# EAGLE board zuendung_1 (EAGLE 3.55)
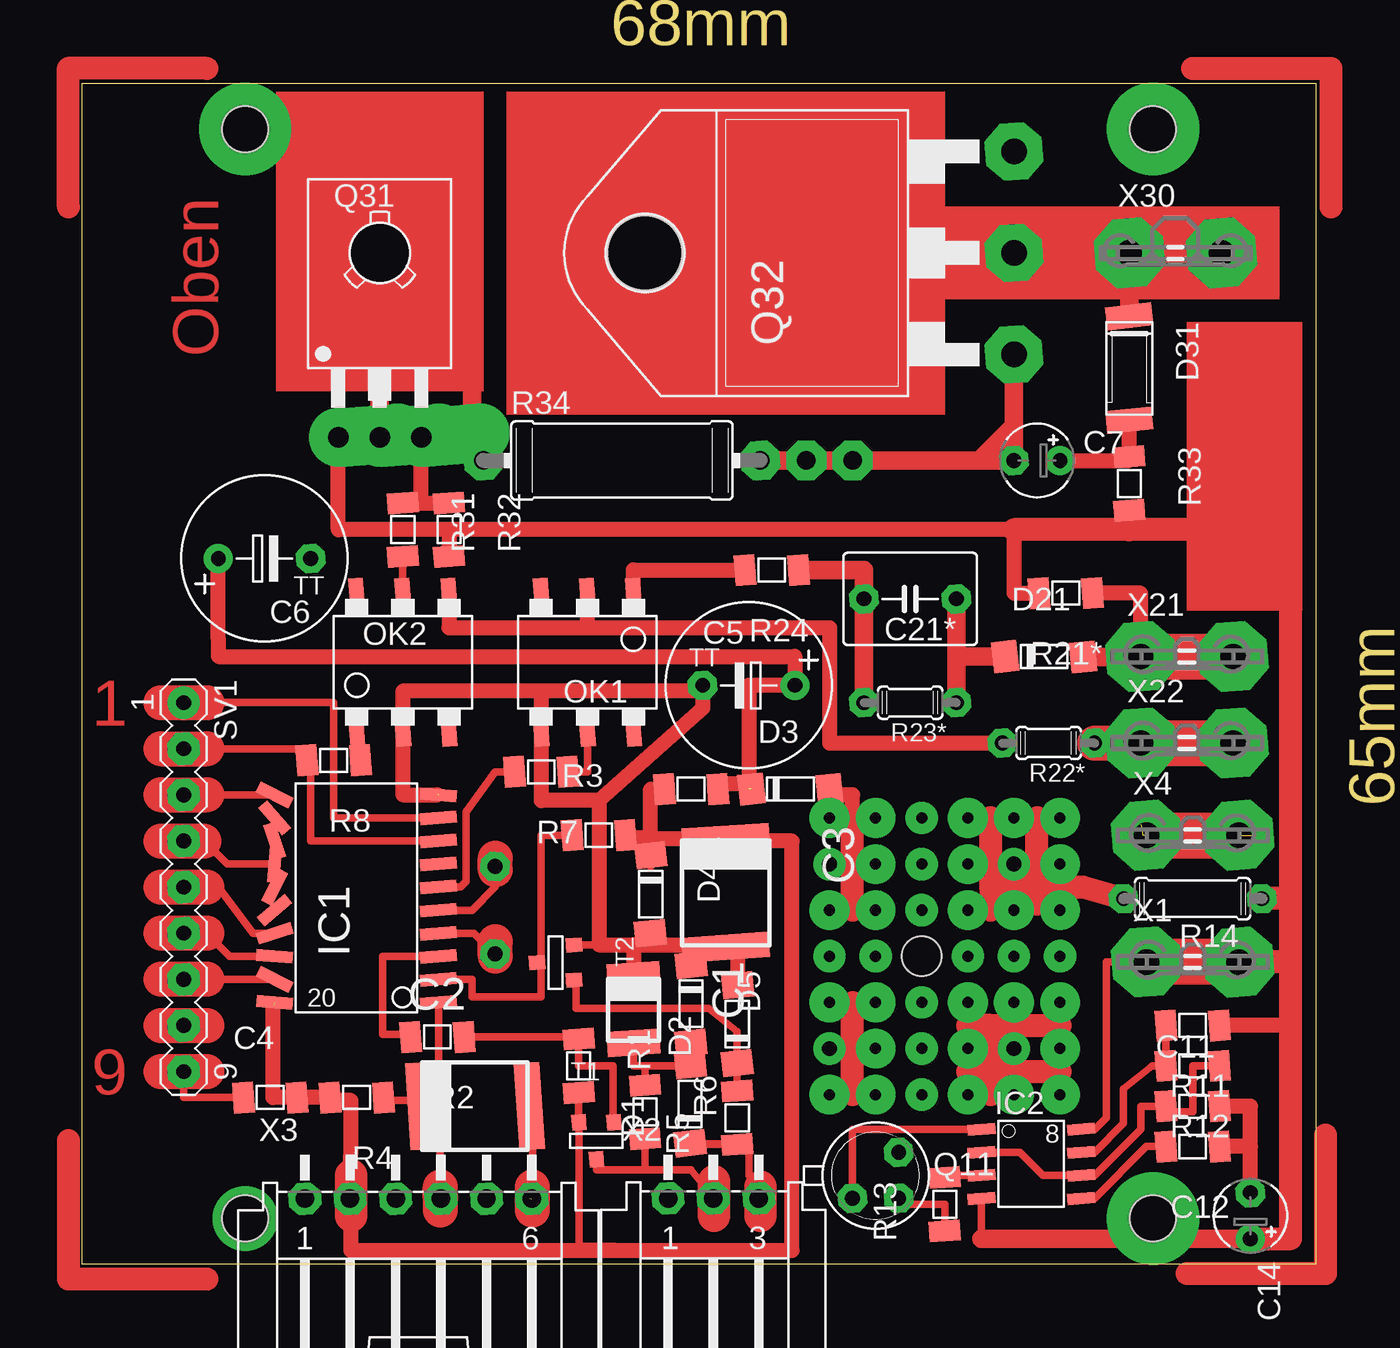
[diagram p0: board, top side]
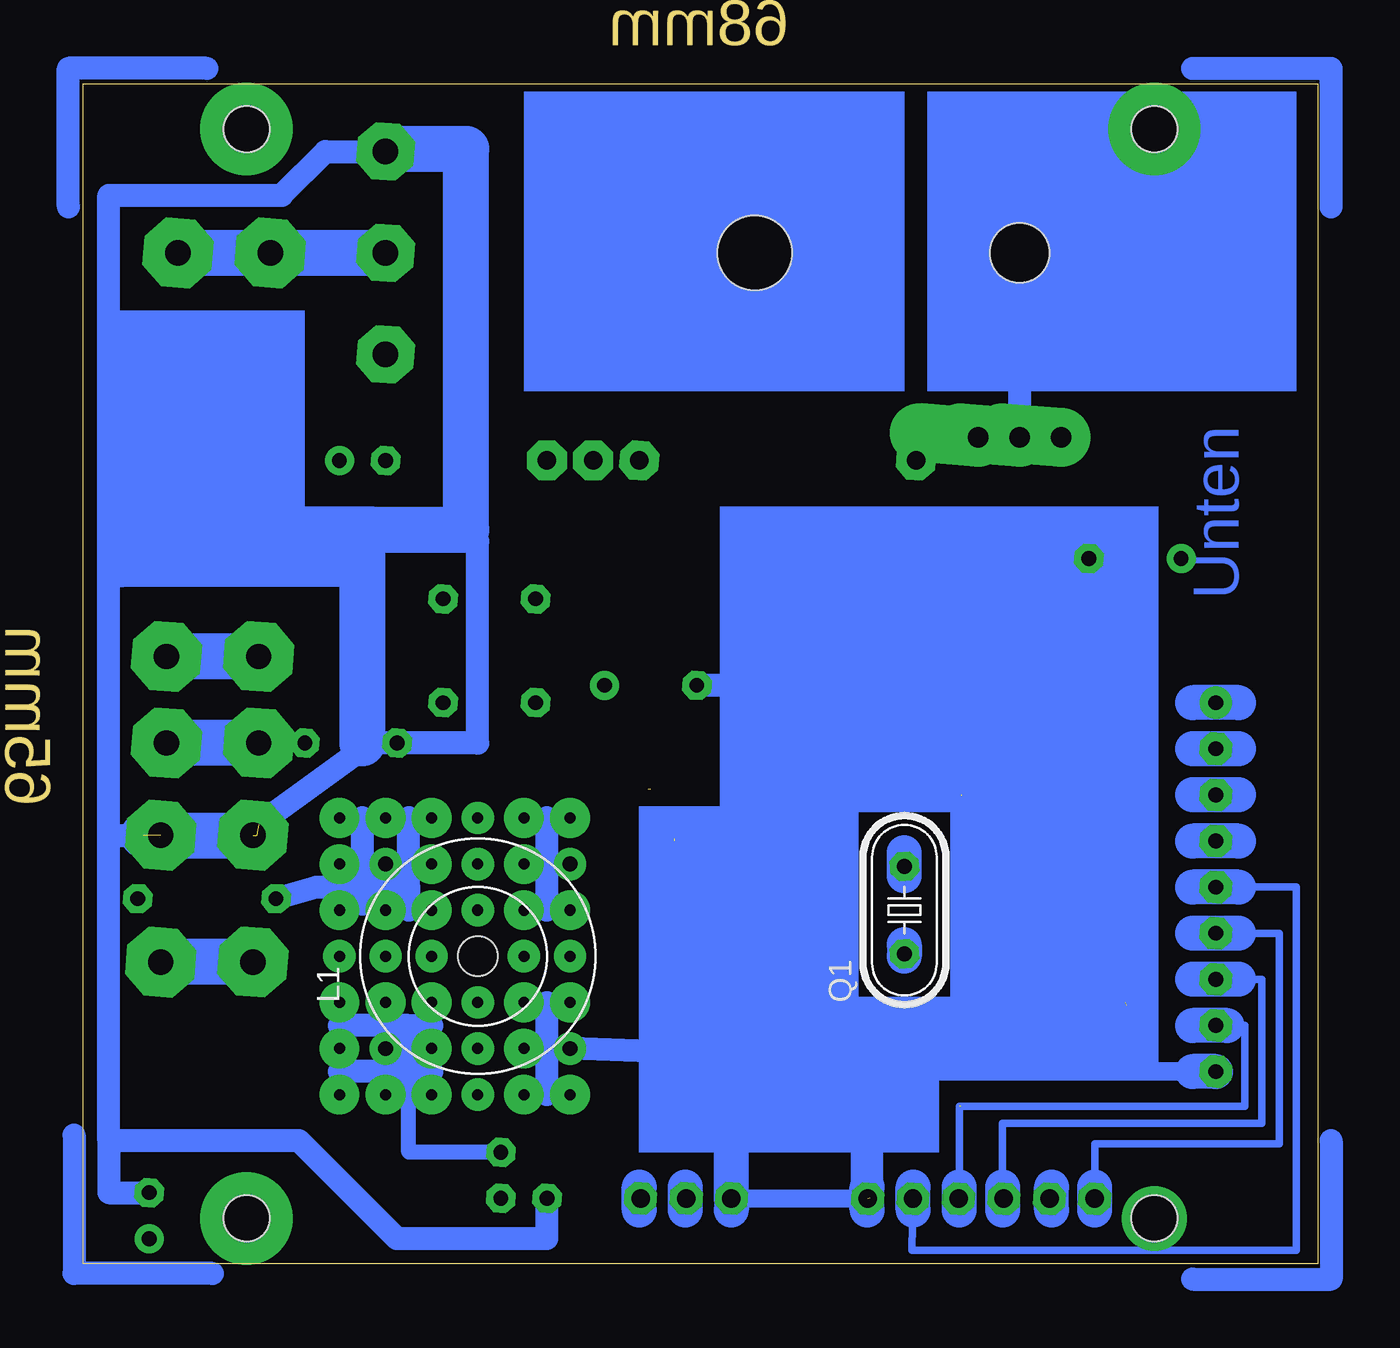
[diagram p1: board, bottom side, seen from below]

Size 68 x 65 mm. Coordinates in mm from the lower left corner, seen from the top.
Outline: 0,0 68,0 68,65 0,65 0,0
Copper layers used: Top, Bottom
Holes 2.54 mm at 9,2.5 59,2.5 59,62.5 9,62.5

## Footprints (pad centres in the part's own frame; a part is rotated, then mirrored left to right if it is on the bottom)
 = smd 1.4 x 2.9 rotated 3.8:  -1.8,0 | smd 1.4 x 2.9 rotated 4:  1.9,0
KO6X5 = smd 1.4 x 4.8 rotated 3.8:  -3,0 | smd 1.4 x 4.8 rotated 4:  3,0
06 = smd 1.143 x 1.702 rotated 4.4:  1.473,0 | smd 1.143 x 1.702 rotated 4.3:  -1.473,0
5D9 = drill 0.813 pad 1.6 octagon:  -2.54,0 | drill 0.813 pad 1.6 round:  2.54,0
2D4 = drill 0.813 pad 1.6 octagon:  -1.27,0 | drill 0.813 pad 1.6 round:  1.27,0
B5 = drill 0.813 pad 1.6 octagon:  -2.54,0;  2.54,0
D-80 = smd 1.397 x 1.702 rotated 6.6:  -2.388,0 | smd 1.397 x 1.702 rotated 5.7:  1.905,-0.025
LF = smd 1.27 x 2.54 rotated 6.6:  -2.857,0 | smd 1.27 x 2.54 rotated 5.7:  2.857,0
-20 = smd 0.66 x 2.007 rotated 4.3:  -5.08,-4.496;  6.35,-4.496 | smd 0.66 x 2.007 rotated 4.4:  -3.81,-4.496;  -5.08,4.521 | smd 0.66 x 2.007 rotated 4.5:  -2.54,-4.496 | smd 0.66 x 2.007 rotated 4.6:  -1.27,-4.496 | smd 0.66 x 2.007 rotated 4.7:  0,-4.496;  1.27,-4.496 | smd 0.66 x 2.007 rotated 4.8:  2.54,-4.496 | smd 0.66 x 2.007 rotated 4.9:  3.81,-4.496 | smd 0.66 x 2.007 rotated 5:  5.08,-4.496 | smd 0.66 x 2.007 rotated 49.3:  5.08,4.521 | smd 0.66 x 2.007 rotated 26.8:  6.35,4.521 | smd 0.66 x 2.007 rotated 71.8:  3.81,4.521 | smd 0.66 x 2.007 rotated 94.3:  2.54,4.521 | smd 0.66 x 2.007 rotated 116.8:  1.27,4.521 | smd 0.66 x 2.007 rotated 139.3:  0,4.521 | smd 0.66 x 2.007 rotated 161.8:  -1.27,4.521 | smd 0.66 x 2.007 rotated 184.3:  -2.54,4.521 | smd 0.66 x 2.007 rotated 206.8:  -3.81,4.521
-8 = smd 0.61 x 1.524 rotated 4.3:  -1.27,-2.743 | smd 0.61 x 1.524 rotated 4.9:  -1.27,2.743 | smd 0.61 x 1.524 rotated 4.4:  0,-2.743 | smd 0.61 x 1.524 rotated 4.5:  1.27,-2.743 | smd 0.61 x 1.524 rotated 4.8:  0,2.743 | smd 0.61 x 1.524 rotated 4.7:  1.27,2.743;  2.54,2.743 | smd 0.61 x 1.524 rotated 4.6:  2.54,-2.743
10X10 = drill 0.813 pad 1.778 round:  -5.08,5.08;  5.08,5.08;  5.08,-5.08;  -5.08,-5.08 | hole 2.184: 0,0
IC06 = smd 0.813 x 1.676 rotated 4.7:  0,3.81;  -2.54,3.81 | smd 0.813 x 1.676 rotated 4.6:  2.54,3.81 | smd 0.813 x 1.676 rotated 4.4:  0,-3.81 | smd 0.813 x 1.676 rotated 4.3:  -2.54,-3.81 | smd 0.813 x 1.676 rotated 4.5:  2.54,-3.81
49U-V = drill 0.813 pad 1.6 octagon:  -2.413,0;  2.413,0
18 = drill 0.813 pad 1.6 octagon:  -1.27,-1.27;  1.27,-1.27;  1.27,1.27
126 = drill 1.118 pad 3.251 offset:  -2.286,-5.08;  0,-5.08;  2.286,-5.08 | hole 3.302: 0,5.08
P3 = drill 1.397 pad 3.15 octagon:  -5.588,-7.62;  0,-7.62;  5.588,-7.62 | hole 4.115: 0,12.7
07/7 = drill 0.813 pad 1.6 octagon:  -3.81,0;  3.81,0
04/5 = drill 0.813 pad 1.6 octagon:  -2.54,0;  2.54,0
14/15 = drill 1.016 pad 2.159 octagon:  -7.62,0;  7.62,0
09-1 = drill 0.813 pad 1.778 round:  -10.16,0 | drill 0.813 pad 1.778 octagon:  -7.62,0;  -5.08,0;  -2.54,0;  0,0;  2.54,0;  5.08,0;  7.62,0;  10.16,0
T-23 = smd 0.787 x 0.889 rotated 4.4:  0.991,1.016 | smd 0.787 x 0.889 rotated 4.3:  -0.94,1.016 | smd 0.787 x 0.889 rotated 4.5:  0.025,-1.016
4,8 = drill 1.397 pad 3.81 octagon:  -2.54,0;  2.54,0
FW3 = drill 1.016 pad 1.778 octagon:  0,1.905;  2.489,1.905;  5.004,1.905
FW6 = drill 1.016 pad 1.778 octagon:  0,1.905;  2.489,1.905;  5.004,1.905;  7.493,1.905;  10.008,1.905;  12.497,1.905
6,3 = drill 1.397 pad 3.81 octagon:  -2.54,0;  2.54,0

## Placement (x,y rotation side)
C1  2æ2/16  []  30.38,14.08 270 top
C2  22/16  [KO6X5]  21.65,8.68 0 top
C3  22/10  [KO6X5]  35.47,20.43 270 top
C4  100n  [06]  10.38,9.16 0 top
C5  470/10  [5D9]  36.73,31.86 0 top
C6  470/10  [5D9]  10.06,38.85 180 top
C7  0,22  [2D4]  52.61,44.24 0 top
C11  2n7  [06]  61.18,8.68 0 top
C12  10n  [06]  61.18,6.46 180 top
C14  47/25  [2D4]  64.36,2.65 270 top
C21*  47n*  [B5]  45.62,36.62 180 top
D1  LL4148  [D-80]  33.5,9.03 90 top
D2  LL4148  [D-80]  36.1,13.45 90 top
D3  LL4148  [D-80]  39.27,26.15 0 top
D4  5V1  [D-80]  31.34,20.11 270 top
D5  LL4148  [D-80]  33.56,14.08 270 top
D21  LL4148  [D-80]  53.24,33.45 0 top
D31  BYM10  [LF]  57.69,49.33 270 top
IC1  AT90S2313  [-20]  15.14,19.48 90 top
IC2  555  [-8]  52.29,6.14 270 top
L1  T1:1/10  [10X10]  46.26,16.94 90 bottom
OK1  SFH601-2SO  [IC06]  27.84,33.13 180 top
OK2  SFH601-2SO  [IC06]  17.68,33.13 0 top
Q1  10.000  [49U-V]  22.77,19.48 90 bottom
Q11  BCY59  [18]  43.72,4.88 0 top
Q31  BD236  [126]  16.41,50.59 0 top
Q32  BD249  [P3]  43.72,55.67 90 top
R1  4K7  [06]  27.37,10.91 270 top
R2  4K7  [06]  19.59,12.49 180 top
R3  4K7  [06]  28.48,23.61 0 top
R4  10K  [06]  15.14,9.16 180 top
R5  4K7  [06]  36.1,8.05 90 top
R6  4K7  [06]  31.02,8.37 270 top
R7  1K  [06]  25.3,27.1 180 top
R8  680  [06]  13.88,27.73 180 top
R9  10  [06]  33.56,26.15 180 top
R11  1k5  [06]  61.18,13.13 180 top
R12  1k5  [06]  61.18,10.91 180 top
R13  3K3  [06]  47.53,3.29 90 top
R14  56  [07/7]  61.18,20.11 180 top
R21*  12K*  [06]  54.2,36.94 180 top
R22*  0*  [04/5]  53.24,28.69 180 top
R23*  100K*  [04/5]  45.62,30.91 180 top
R24  330  [06]  38.01,38.21 180 top
R31  330  [06]  17.68,40.44 270 top
R32  1K  [06]  20.23,40.44 270 top
R33  270  [06]  57.69,42.98 270 top
R34  120/1  [14/15]  29.75,44.24 0 top
SV1  MA09-1  [09-1]  5.62,20.75 270 top
T1  BC807  [T-23]  28.32,6.78 0 top
T2  BC817  [T-23]  26.1,16.62 270 top
U$8  [2]  -0.09,-0.21 0 top
U$9  [2]  67.85,0.11 90 top
U$10  [2]  68.17,65.2 180 top
U$11  [2]  -0.09,65.2 270 top
X1  ST4,8  [4,8]  61.18,16.62 0 top
X2  MSFW3  [FW3]  32.29,1.7 0 top
X3  MSFW6  [FW6]  12.29,1.68 0 top
X4  ST4,8  [4,8]  61.18,23.61 0 top
X21  ST4,8  [4,8]  60.87,33.45 0 top
X22  ST4,8  [4,8]  60.87,28.69 0 top
X30  ST6,3  [6,3]  60.23,55.67 0 top

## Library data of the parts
C1-C4 C11 C12 D1-D5 D21 D31 R1-R9 R11-R13 R21* R24 R31-R33 T1 T2 = SMD
C5-C7 C14 = CAP-TANT
C21* = CAP
IC1 IC2 = SMD-IC
L1 = TRAFO-R
OK1 OK2 = OPTOCPL
Q1 = QUARTZ
Q11 Q32 = NPN
Q31 = PNP
R14 R22* R23* R34 = R
SV1 = CON-LSTB
U$8-U$11 = MARKS
X1 X4 X21 X22 X30 = CON-RIB
X2 X3 = CON-MSF

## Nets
+12V: C14. IC2. Q31. R11. R14. R21*. R32. R33. X1.
BT1: R1. R2. T1.
BT2: D2. R5. T2.
D21K: C21*. D21. R23*.
DGND: C1. C2. C3. C4. C5. C6. D2. D4. D5. IC1. L1. OK1. OK2. SV1. T2. X2. X3.
GND: C11. C12. C14. IC2. OK1. OK2. Q11. Q32. R22*. X4.
INT0: OK1. R7.
MISO: IC1. SV1. X3.
MOSI: IC1. SV1. X3.
N$1: C7. D31. R33.
N$2: Q31. R31. R32.
N$3: OK2. R31.
N$4: IC2. R13.
N$5: C12. IC2.
N$6: L1. R14.
N$7: C5. C6. D3. R9.
N$8: OK1. R24.
N$9: Q31. R34.
N$10: C7. Q32. R34.
N$11: D3. L1.
N$14: C11. IC2. R12.
N$15: IC2. R11. R12.
N$16: C1. D1. D5. R6.
N$29: C21*. R23*. R24.
N$46: L1. Q11.
N$48: Q11. R13.
OUT0: OK2. R8.
PB2: IC1. SV1.
PD0: IC1. R3. T2.
PD1: IC1. R2.
PD2: IC1. R7.
PD4: IC1. R8. SV1.
PD5: IC1. SV1.
PD6: IC1. SV1.
RESET: C2. IC1. R4. SV1. X3.
RXD: D1. R5. X2.
SCK: IC1. SV1. X3.
TXD: R6. T1. X2.
VCC: C3. C4. D4. IC1. R1. R3. R4. R9. T1. X3.
X6: D31. Q32. X30.
X21: D21. R21*. X21.
X22: R22*. X22.
XTAL1: IC1. Q1.
XTAL2: IC1. Q1.

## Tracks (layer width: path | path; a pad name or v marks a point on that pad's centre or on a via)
+12V
  Top 0.406: 55.04,7.41 55.78,7.41 56.42,8.05 56.42,16.62 | 58.01,16.62 56.42,16.62 | 49.55,1.38 49.55,3.61 | 58.64,16.62 56.42,16.62
  Top 0.813: 52.72,36.94 51.34,36.94 51.34,40.44 20.23,40.44 | 14.13,45.52 14.13,40.44 20.23,40.44 | 20.23,40.44 20.23,38.96 | 57.69,40.44 61.5,40.44 | 66.58,13.13 R11.
  Top 1.016: 57.69,40.44 57.69,41.5 | 49.55,1.38 C14.
  Top 1.27: C14. 66.58,1.38 66.58,13.13 66.58,16.62 | 51.34,40.44 57.69,40.44 66.58,40.44 66.58,20.11 | 66.58,16.62 64.36,16.62 X1. | 66.58,20.11 64.99,20.11 | 66.58,16.62 66.58,20.11
  Top 2.54: 58.01,16.62 58.64,16.62 64.36,16.62
BT1
  Top 0.406: 27.37,12.5 27.53,12.5 | 27.37,12.5 R1. 27.37,10.91 29.27,10.91 29.27,7.73 29.31,7.73 29.31,7.8 | R2. | R2. 27.37,12.5
BT2
  Top 0.406: 36.1,9.52 36.1,11.06 36.1,12.81 34.51,14.08 27.21,14.08 27.21,15.63 27.11,15.63
D21K
  Top 1.016: 50.86,33.45 48.16,33.45 48.16,30.91 48.16,36.62
DGND  (2 unrouted)
  Top 0.406: SV1. 5.62,9.16 C4. | C2. 24.83,10.43 24.83,3.76 24.67,3.61 | 17.68,31.55 17.68,29.32 | 27.11,17.56 28.23,17.57 28.48,17.57 | 31.66,17.57 D4. | 35.47,17.57 36.12,17.57
  Top 0.813: 25.3,31.55 17.68,31.55 17.68,25.83 19.59,25.83 | 25.3,31.55 25.3,29.32 25.3,25.51 28.48,25.51 | 36.12,17.57 D2. | 30.38,17.57 30.38,15.88 | 28.48,25.51 28.48,17.57 30.38,17.57 | 30.38,17.57 31.66,17.57 35.47,17.57 | 28.48,25.51 34.2,30.59 34.2,31.55 | 34.2,31.86 34.2,31.55 | 34.2,31.55 25.3,31.55 | 35.47,17.57 C3. | 33.56,16.47 33.56,17.57 35.47,17.57
  Bottom 0.406: 24.83,3.61 X3. 24.99,3.59 24.99,3.61 24.67,3.61 | 32.29,3.61 32.29,11.54
  Bottom 0.813: 12.61,38.85 12.61,31.86 34.2,31.86
  Bottom 1.016: 6.89,10.59 24.83,10.59 | X3. 32.29,3.61 | 32.29,21.38 28.48,21.38
  Bottom 1.27: 34.2,31.86 32.29,31.86 32.29,21.38 | 32.29,11.54 L1.
  Bottom 1.778: 24.83,10.59 24.83,3.61
  Bottom 1.93: 32.29,21.38 32.29,3.61 32.29,2.97 | SV1. 6.89,10.59
GND  (3 unrouted)
  Top 0.406: 49.55,7.41 42.45,7.41 42.45,3.61
  Top 0.813: R22*. 41.18,28.69 41.18,35.04 27.84,35.04 | 20.23,36.94 20.23,35.04 27.84,35.04 | 27.84,35.04 27.84,36.94 | 62.66,8.68 64.36,8.68 64.36,6.46 | 64.36,6.46 C12. | 64.36,3.92 64.36,6.46
  Bottom 1.27: Q32. 54.64,61.26 57.05,58.85 66.58,58.85 66.58,23.61 | 58.33,24.19 52.61,28.37 52.61,28.69 R22*. | 66.58,23.61 64.67,23.61 58.43,23.61 | 66.58,6.78 66.58,23.61 | 66.58,6.78 66.58,3.92 64.36,3.92 | 42.45,3.61 42.45,1.38 50.7,1.38 56.1,6.78 66.58,6.78
  Bottom 2.54: 64.67,23.61 58.01,23.61
INT0
  Top 0.406: R7. 27.84,27.1 27.84,29.32
MISO
  Top 0.406: 5.62,18.21 6.89,18.21 8.16,16.94 10.62,16.94 10.7,16.94
  Top 1.93: 6.89,18.21 4.35,18.21
  Bottom 0.406: 5.62,18.21 4.35,18.21 2.13,18.21 2.13,6.62 12.29,6.62 12.29,3.59
  Bottom 1.93: 4.35,18.21 6.89,18.21
MOSI
  Top 0.406: 5.62,20.75 7.53,20.75 9.43,18.21 10.62,18.21
  Bottom 0.406: 22.3,3.59 22.36,0.75 1.17,0.75 1.17,20.75 4.35,20.75 5.62,20.75
  Bottom 1.93: 4.35,20.75 6.89,20.75
N$1
  Top 0.406: 57.69,44.24 R33.
  Top 0.813: R33. D31. | C7. 57.69,44.24
N$2
  Top 0.406: 17.68,41.7 R32. 18.7,42.02
  Top 0.813: 18.7,42.02 Q31. | R31. R32.
N$3
  Top 0.406: 17.68,36.94 17.68,38.96
N$4
  Top 0.406: 49.55,4.88 47.53,4.88 47.53,4.76
N$5
  Top 0.406: 59.71,6.46 58.64,6.46 55.78,3.61 IC2. 54.83,3.61
N$6
  Top 0.813: 51.66,20.75 51.34,21.07 51.34,22.02
  Top 1.27: R14. 55.15,20.75 51.66,20.75
  Bottom 1.27: 54.2,20.75 55.15,20.75 R14.
N$7  (1 unrouted)
  Top 0.406: 36.89,26.47 36.89,26.15 | R9. 35.03,26.47
  Top 0.813: 35.03,26.47 36.89,26.47 | 36.73,26.15 36.73,31.86 C5. 39.27,33.45 7.53,33.45 7.53,34.4 C6.
N$8
  Top 0.813: 36.53,38.21 30.38,38.21 30.38,36.94
N$9
  Top 1.016: 22.13,44.24 21.5,44.88 21.5,49.33 16.41,49.33 16.41,45.52
  Bottom 1.27: 16.41,45.52 16.41,49.33
N$10  (via drill 1.02 pad 2.18)
  Top 1.016: 51.34,46.15 51.34,44.24 47.53,44.24 | 51.34,46.15 51.34,50.09 | R34. v39.91,44.24 v42.45,44.24 47.53,44.24 | 51.34,46.15 49.44,44.24 47.53,44.24
N$11
  Top 0.406: 41.18,26.15 D3. 41.18,25.83
  Top 0.813: 41.18,25.83 42.45,25.83 42.45,22.02 41.18,22.02
N$12  (via drill 0.61 pad 2.18)
  other vias: 43.72,22.02
N$13
  Top 1.93: 4.35,20.75 6.89,20.75
N$14
  Top 0.406: R12. 61.18,10.91 61.18,8.37 59.59,8.37 59.59,8.68 C11. 58.33,8.68 58.33,7.41 55.78,4.88 55.04,4.88 52.93,4.88 51.66,6.14 49.55,6.14
N$15
  Top 0.406: 59.71,10.91 59.71,13.13 | 59.71,10.91 59.59,10.91 | 59.71,10.91 58.96,10.91 57.37,9.64 57.37,7.73 55.78,6.14 55.04,6.14
N$16
  Top 0.406: 31.02,10.91 30.38,10.91 C1. | R6. 31.02,10.91 | 31.02,10.91 33.56,10.91
  Top 0.813: D1. 33.56,10.91 33.53,10.91 D5.
N$17
  Top 1.93: 4.35,13.13 6.89,13.13
N$18
  Top 1.93: 4.35,10.59 6.89,10.59
N$19
  Top 1.93: 22.77,16.94 22.77,17.73
N$20  (via drill 0.61 pad 2.18)
  other vias: 48.8,22.02
N$21
  Bottom 1.93: 12.29,2.97 12.29,4.24
N$22
  Bottom 1.93: 14.67,2.97 14.67,4.24
N$23
  Bottom 1.93: 19.75,2.97 19.75,4.24
N$24
  Bottom 1.93: 22.29,2.97 22.29,4.24
N$25
  Bottom 1.93: 24.83,2.97 24.83,4.24
N$26
  Bottom 1.93: 34.83,2.97 34.83,4.24
N$27
  Bottom 1.93: 37.37,2.97 37.37,4.24
N$28
  Bottom 1.93: 4.35,30.91 6.89,30.91
N$29
  Top 1.016: R23*. C21*. 43.09,38.21 R24.
N$30
  Bottom 1.93: 4.35,28.37 6.89,28.37
N$31
  Bottom 1.93: 4.35,25.83 6.89,25.83
N$32
  Bottom 1.93: 4.35,23.29 6.89,23.29
N$33
  Bottom 1.93: 22.77,21.38 22.77,22.66
N$34
  Bottom 1.93: 22.77,17.57 22.77,16.94
N$35
  Bottom 2.54: 51.34,61.39 46.9,61.39 46.9,40.44 52.61,40.44 52.61,28.69
N$36
  Bottom 2.54: 51.98,40.44 65.94,40.44
N$37
  Bottom 2.54: 52.93,38.53 65.94,38.53
N$38
  Bottom 1.27: 46.26,39.8 46.26,28.69 51.98,28.69
N$39  (via drill 0.61 pad 2.18)
  other vias: 51.34,24.56
N$40
  Top 1.93: 24.83,2.97 24.83,4.24
N$41  (via drill 2.54 pad 5.08)
  other vias: 59,2.5
N$42  (via drill 2.54 pad 5.08)
  other vias: 59,62.5
N$43  (via drill 2.54 pad 5.08)
  other vias: 9,62.5
N$44  (via drill 2.54 pad 2.54)
  other vias: 9,2.5
N$45
  Top 1.778: 34.83,2.65 34.83,4.56
N$46
  Bottom 0.813: Q11. 50.07,6.14 50.07,11.86 51.34,11.86 51.66,11.86
N$47  (via drill 0.61 pad 2.18)
  other vias: 53.88,22.02
N$48
  Top 0.406: R13. 47.53,3.29 44.99,3.29 44.99,3.61
N$49  (via drill 0.61 pad 2.18)
  other vias: 48.8,19.48
N$50  (via drill 0.61 pad 2.18)
  other vias: 51.34,19.48
N$51  (via drill 0.61 pad 2.18)
  other vias: 53.88,19.48
N$52  (via drill 0.61 pad 2.18)
  other vias: 41.18,19.48
N$53  (via drill 0.61 pad 2.18)
  other vias: 43.72,19.48
N$54  (via drill 0.61 pad 2.18)
  other vias: 41.18,14.4
N$55  (via drill 0.61 pad 2.18)
  other vias: 43.72,14.4
N$56  (via drill 0.61 pad 2.18)
  other vias: 48.8,14.4
N$57  (via drill 0.61 pad 2.18)
  other vias: 51.34,14.4
N$58  (via drill 0.61 pad 2.18)
  other vias: 53.88,14.4
N$59  (via drill 0.61 pad 2.18)
  other vias: 48.8,11.86
N$60  (via drill 0.61 pad 2.18)
  other vias: 43.72,11.86
N$61  (via drill 0.61 pad 2.18)
  other vias: 41.18,9.32
N$62  (via drill 0.61 pad 2.18)
  other vias: 43.72,9.32
N$63  (via drill 0.61 pad 2.18)
  other vias: 43.72,24.56
N$64  (via drill 0.61 pad 2.18)
  other vias: 48.8,24.56
N$65  (via drill 0.61 pad 2.18)
  other vias: 41.18,24.56
N$66  (via drill 0.61 pad 2.18)
  other vias: 53.88,11.86
N$67  (via drill 0.61 pad 2.18)
  other vias: 48.8,9.32
N$68
  Top 1.27: 42.45,19.48 42.45,24.56
N$69
  Top 1.27: 50.07,20.75 50.07,24.56 | 50.07,20.75 50.07,19.48 | 50.07,20.75 53.88,20.75
N$70
  Top 1.27: 42.45,9.32 42.45,14.4
N$71
  Top 1.27: 50.07,13.13 48.8,13.13 | 50.07,13.13 53.88,13.13 | 50.07,9.32 50.07,13.13
N$72
  Bottom 1.27: 42.45,19.48 42.45,24.56
N$73
  Bottom 1.27: 50.07,20.75 50.07,24.56 | 50.07,20.75 50.07,19.48 | 50.07,20.75 53.88,20.75
N$74
  Bottom 1.27: 42.45,9.32 42.45,14.4
N$75
  Bottom 1.27: 50.07,13.13 48.8,13.13 | 50.07,13.13 53.88,13.13 | 50.07,9.32 50.07,13.13
N$76
  Top 2.54: 58.01,23.61 63.72,23.61
N$77  (via drill 0.61 pad 2.18)
  other vias: 51.34,9.32
N$78  (via drill 0.61 pad 2.18)
  other vias: 53.88,9.32
N$79  (via drill 0.61 pad 1.78)
  other vias: 46.26,24.56
N$80  (via drill 0.61 pad 1.78)
  other vias: 46.26,22.02
N$81  (via drill 0.61 pad 1.78)
  other vias: 46.26,19.48
N$82  (via drill 0.61 pad 1.78)
  other vias: 46.26,14.4
N$83  (via drill 0.61 pad 1.78)
  other vias: 46.26,11.86
N$84  (via drill 0.61 pad 1.78)
  other vias: 46.26,9.32
N$85  (via drill 0.61 pad 1.78)
  other vias: 48.8,16.94
N$86  (via drill 0.61 pad 1.78)
  other vias: 51.34,16.94
N$87  (via drill 0.61 pad 1.78)
  other vias: 53.88,16.94
N$88  (via drill 0.61 pad 1.78)
  other vias: 41.18,16.94
N$89  (via drill 0.61 pad 1.78)
  other vias: 43.72,16.94
N$90  (via drill 0.61 pad 1.78)
  other vias: 46.26,16.94
N$91
  Top 1.778: 37.37,2.65 37.37,4.24
N$95
  Bottom 2.54: 58.01,16.62 64.36,16.62
N$97
  Top 1.27: 48.8,10.59 53.88,10.59
N$98  (via drill 0.61 pad 2.18)
  other vias: 53.88,24.56
N$99
  Top 1.27: 52.61,19.8 52.61,24.56
N$100
  Bottom 1.27: 52.61,24.56 52.61,20.11 52.61,19.8
N$101
  Bottom 1.27: 48.8,10.59 53.88,10.59
OUT0
  Top 0.406: R8. 15.14,27.73 15.14,29.32
PB2
  Top 0.406: 5.62,23.29 6.73,23.29 8,22.02 10.62,22.02 10.7,22.02
  Top 1.93: 4.35,23.29 6.73,23.29
PD0
  Top 0.406: R3. 25.3,23.61 25.3,16.62 | 25.3,16.62 25.3,16.46 | T2. 25.3,16.6 25.3,16.62 | 25.3,16.62 25.3,14.72 21.5,14.72 21.5,15.67 19.64,15.67
PD1
  Top 0.406: 19.64,16.94 16.57,16.94 16.57,12.65 18.12,12.65 18.12,12.5
PD2
  Top 0.406: 19.59,20.75 19.64,20.75 20.86,20.75 21.18,21.07 21.18,24.88 22.77,27.1 23.83,27.1
PD4
  Top 0.406: 5.62,28.37 6.89,28.37 12.29,28.37 | 19.91,23.29 19.64,23.29 12.61,23.29 12.61,28.37 12.29,28.37 | 12.29,28.37 12.4,27.73
  Top 1.93: 4.35,28.37 6.89,28.37
PD5
  Top 0.406: 5.62,30.91 6.89,30.91 13.88,30.91 13.88,24.56 19.64,24.56
  Top 1.93: 4.35,30.91 6.89,30.91
PD6
  Top 0.406: 10.7,25.83 10.62,25.83 6.89,25.83 5.62,25.83
  Top 1.93: 4.35,25.83 6.89,25.83
RESET  (1 unrouted)
  Top 0.406: 18.65,8.68 18.65,9 16.62,9 R4. | 18.65,8.68 18.64,8.68 | 19.64,14.4 19.64,8.68 18.65,8.68 | 19.75,3.76 19.75,8.68 18.65,8.68 | 19.59,3.59 19.59,3.29 | 19.78,3.59 19.59,3.59 | 19.75,3.61 19.59,3.61 19.59,3.59
  Top 1.93: 19.75,4.24 19.75,3.76 19.75,3.61 19.75,2.97
  Bottom 0.406: 5.62,13.13 4.99,13.13 4.03,13.13 4.03,8.68 19.75,8.68 19.75,3.76
  Bottom 1.93: 4.99,13.13 6.89,13.13
RXD
  Top 0.406: 33.56,6.58 33.5,6.64 36.73,6.61 36.73,4.88 37.37,3.61 X2. | 33.56,6.58 R5. | 33.56,6.58 33.56,6.46
SCK
  Top 0.406: 5.62,15.67 6.89,15.67 10.62,15.67
  Top 1.93: 6.89,15.67 4.35,15.67
  Bottom 0.406: 17.37,4.24 17.37,7.73 3.08,7.73 3.08,15.67 4.35,15.67 5.62,15.67 | 17.37,3.61 17.29,3.59
  Bottom 1.93: 17.37,4.24 17.37,3.61 17.37,2.97 | 4.35,15.67 6.89,15.67
TXD
  Top 0.406: 34.78,3.61 34.83,3.61 33.56,5.19 31.02,5.19 | 31.02,5.19 31.02,6.89 | T1. 28.35,5.19 31.02,5.19
VCC  (2 unrouted)
  Top 0.406: 31.34,26.15 32.09,26.15 | 31.34,22.5 31.34,21.86 | 14.78,3.76 14.67,3.76 | 14.78,3.76 14.78,3.59 | 14.83,2.65 14.83,3.76 14.78,3.76 | 31.34,23.43 31.34,23.45 | 30.11,23.45 29.95,23.61 | 27.37,7.73 27.38,7.73 27.38,7.8 27.38,0.75 | 27.37,7.73 27.37,9.43 | 27.37,7.73 27.21,7.73 | 29.43,0.75 | 29.42,0.75 29.43,0.75
  Top 0.813: 31.34,26.15 31.34,23.45 30.11,23.45 | 35.47,23.43 31.34,23.43 31.34,22.5 | 29.43,0.75 39.12,0.75 39.12,23.29 35.47,23.29 | 14.83,2.65 14.83,0.75 29.42,0.75 27.38,0.75 | 10.54,14.24 10.54,9.16 11.86,9.16 13.67,9.16 13.67,9 14.83,9 14.83,6.78 14.78,3.76
  Top 1.778: 14.83,2.65 14.83,4.88
X6
  Top 0.406: 57.69,55.67 57.69,52.18
  Top 1.016: 57.69,55.67 57.69,52.18
  Top 2.54: 51.34,55.67 57.69,55.67 X30.
  Bottom 2.54: 51.34,55.67 X30.
X21
  Top 0.406: 58.3,33.42 58.33,33.45 | R21*. 55.78,36.94
  Top 0.813: D21. 55.15,33.45 58.33,33.45 58.33,36.94 R21*.
  Top 1.016: D21. 58.3,33.42
  Top 2.54: 58.33,33.45 X21.
  Bottom 2.54: 58.33,33.45 X21.
X22
  Top 1.93: 55.78,28.69 58.33,28.69
  Top 2.54: 58.33,28.69 X22.
  Bottom 0.406: 58.33,28.69 X22.
  Bottom 1.016: 55.78,28.69 58.33,28.69
  Bottom 2.54: 58.33,28.69 X22.
XTAL1
  Top 0.406: 19.64,19.48 21.5,19.48 22.77,20.75 22.77,21.7 Q1. 22.77,22.34
  Top 1.93: 22.77,21.7 22.77,22.34
XTAL2
  Top 0.406: 19.59,18.21 19.64,18.21 21.62,18.21 22.77,17.07
(copper drawn outside any net)
  shapes: Bottom area x8, Top area x4

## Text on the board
Top: Oben | 1 | 9
Bottom: Unten
Dimension: 68mm | 65mm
